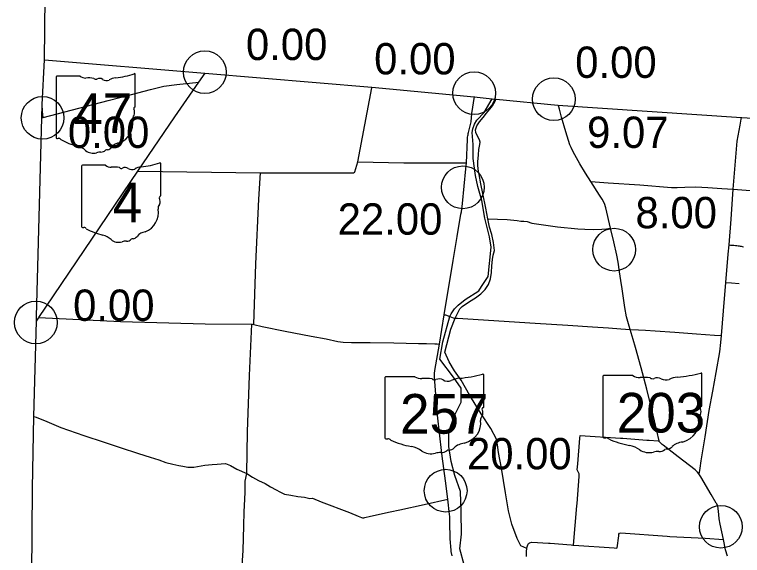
# Model space of a CAD drawing. Extents: x 1597222 to 1925846, y 496284 to 911751.
# Drawn here: x 1759112 to 1784691, y 873644 to 892633 of the extents above; entities that cross this region are included whole.
import ezdxf

# ---------------------------------------------------------------- set-up
doc = ezdxf.new("R2010")
doc.units = 0
for name, color, linetype in [('Default', 7, 'Continuous'), ('GM_X_Adjacent_County', 7, 'Continuous'), ('GM_X_County', 7, 'Continuous'), ('GM_X_County_Road', 7, 'Continuous'), ('GM_X_State_Route', 7, 'Continuous'), ('GM_X_State_Shield', 7, 'Continuous'), ('GM_X_Township', 7, 'Continuous'), ('GM_X_Township_Road', 7, 'Continuous')]:
    doc.layers.add(name, color=color, linetype=linetype)

msp = doc.modelspace()

# ---------------------------------------------------------------- linework, layer by layer
at = {"layer": 'Default'}
for centre in [(1765798, 890612), (1765798, 890612), (1775265, 889876), (1775265, 889876), (1778064, 889660), (1778064, 889660), (1760098, 889010), (1760098, 889010), (1774865, 886568), (1780183, 884380), (1759862, 881825), (1759862, 881825), (1774262, 875917), (1783934, 874652)]:
    msp.add_circle(centre, 750, dxfattribs=at)
at = {"layer": 'GM_X_Adjacent_County'}
msp.add_line((1760161, 891042), (1760364, 911751), dxfattribs=at)
at = {"layer": 'GM_X_County'}
msp.add_lwpolyline([(1759615, 862978), (1759631, 865937), (1759690, 868390), (1759745, 876009), (1759795, 878524), (1759881, 881868), (1759886, 882027), (1760071, 889009), (1760084, 889480), (1760161, 891042), (1765804, 890577), (1771666, 890080), (1775269, 889747), (1775894, 889674), (1776032, 889658), (1778209, 889456), (1784657, 889014), (1789933, 888711), (1791146, 888682), (1797651, 888237), (1803655, 887971)], dxfattribs=at)
at = {"layer": 'GM_X_County_Road'}
for points in [[(1783164, 876512), (1783184, 876554), (1783209, 876711), (1783243, 876961), (1783384, 877811), (1783523, 878729), (1783651, 879411), (1783765, 880071), (1783893, 880796), (1783932, 881116), (1783954, 881366), (1784027, 882233), (1784112, 883231), (1784194, 884219), (1784219, 884544), (1784290, 885451), (1784371, 886499), (1784505, 888183), (1784615, 888751), (1784662, 889026)], [(1779364, 886770), (1779967, 886729), (1781087, 886653), (1782198, 886565), (1782396, 886560), (1782670, 886574), (1783048, 886584), (1783473, 886564), (1783964, 886527), (1784371, 886499), (1786660, 886325), (1787926, 886227), (1788905, 886151), (1789695, 886094), (1789778, 886088), (1790812, 886013), (1791205, 885983), (1792690, 885877), (1793992, 885783), (1794775, 885730), (1796902, 885573), (1797304, 885549), (1797451, 885547), (1797502, 885545)], [(1759969, 881997), (1762841, 881858), (1765814, 881778), (1767451, 881759), (1767471, 881758), (1767516, 881753), (1767813, 881684), (1768617, 881522), (1769536, 881337), (1770062, 881247), (1770477, 881159), (1770666, 881130), (1770953, 881125), (1771606, 881121), (1772443, 881104), (1773313, 881088), (1773587, 881081), (1773877, 881076), (1773962, 881074), (1774048, 881064)], [(1774211, 882090), (1774252, 882089), (1774404, 882033)], [(1774404, 882033), (1774406, 882032), (1774523, 881989), (1774565, 881978), (1774598, 881976), (1774681, 881977), (1777408, 881796), (1778560, 881723), (1779427, 881668), (1779984, 881633), (1780423, 881605), (1780749, 881582)], [(1759795, 878524), (1759874, 878494), (1760252, 878350), (1760733, 878141), (1761552, 877854), (1762256, 877623), (1762819, 877435), (1763473, 877228), (1763875, 877098), (1764180, 876995), (1764428, 876912), (1764673, 876852), (1764882, 876805), (1765024, 876776), (1765203, 876738), (1765411, 876747), (1765804, 876809), (1766052, 876831), (1766236, 876847), (1766368, 876855), (1766526, 876867), (1766703, 876800), (1766927, 876678), (1767271, 876519)], [(1767271, 876519), (1767477, 876397), (1767681, 876278), (1767921, 876172), (1768111, 876051), (1768305, 875950), (1768436, 875882), (1768593, 875793), (1768820, 875758), (1769062, 875716), (1769301, 875685), (1769490, 875642), (1769580, 875657), (1769884, 875528), (1770879, 875150), (1771192, 875019), (1771304, 874972), (1771344, 874966), (1771384, 874967), (1771424, 874974), (1771622, 875018), (1772316, 875174), (1772655, 875249), (1773509, 875437), (1774333, 875620)]]:
    msp.add_lwpolyline(points, dxfattribs=at)
at = {"layer": 'GM_X_State_Route'}
for points in [[(1759881, 881868), (1759956, 881980), (1759969, 881997), (1763443, 887141), (1764744, 889038), (1765591, 890255), (1765808, 890573)], [(1760071, 889009), (1760118, 889022), (1762397, 889618), (1763225, 889831), (1763889, 890004), (1764355, 890118), (1764820, 890175), (1765591, 890255)], [(1774491, 873632), (1774460, 873783), (1774453, 873834), (1774417, 874231), (1774413, 874823), (1774404, 875011), (1774397, 875080), (1774333, 875620), (1774258, 876258), (1774139, 877129), (1774064, 877743), (1773968, 878674), (1773866, 879905), (1773869, 880029), (1773882, 880140), (1774048, 881064), (1774211, 882090), (1774530, 884003), (1774667, 884846), (1774801, 885624), (1774814, 885707), (1774851, 886003), (1774976, 887219), (1774992, 887423), (1775028, 888248), (1775030, 888289), (1775035, 888331), (1775040, 888372), (1775048, 888413), (1775057, 888454), (1775067, 888494), (1775128, 888732), (1775139, 888776), (1775154, 888865), (1775187, 889163), (1775276, 889757)], [(1784162, 873624), (1784100, 873843), (1784021, 874208), (1783910, 874738), (1783876, 874927), (1783859, 875086), (1783838, 875289), (1783833, 875317), (1783827, 875344), (1783809, 875398), (1783786, 875450), (1783772, 875475), (1783588, 875783), (1783232, 876403), (1783164, 876512), (1783115, 876570), (1783035, 876646), (1782427, 877101), (1781907, 877510), (1781873, 877541), (1781822, 877589), (1781780, 877630), (1781764, 877670), (1781516, 878719), (1781330, 879483), (1781130, 880233), (1780935, 880943), (1780851, 881229), (1780749, 881582), (1780714, 881694), (1780668, 881862), (1780620, 882022), (1780562, 882353), (1780462, 883009), (1780418, 883294), (1780375, 883601), (1780321, 883942), (1780275, 884187), (1780166, 884660), (1780054, 885130), (1779891, 885844), (1779879, 885886), (1779851, 885966), (1779818, 886043), (1779756, 886154), (1779666, 886298), (1779364, 886770), (1779176, 887069), (1778977, 887392), (1778738, 887817), (1778667, 887962), (1778627, 888061), (1778487, 888517), (1778336, 889030), (1778262, 889312), (1778237, 889390), (1778211, 889454)]]:
    msp.add_lwpolyline(points, dxfattribs=at)
at = {"layer": 'GM_X_State_Shield'}
for p, q in [((1760571, 890435), (1760571, 888322)), ((1760571, 890435), (1760571, 888322)), ((1761414, 890471), (1760599, 890471)), ((1761414, 890471), (1760599, 890471)), ((1763356, 889418), (1763356, 890524)), ((1763356, 889418), (1763356, 890524)), ((1763355, 889418), (1763356, 889418)), ((1763355, 889418), (1763356, 889418)), ((1762312, 887343), (1761496, 887343)), ((1762312, 887343), (1761496, 887343)), ((1764253, 886290), (1764253, 887395)), ((1764253, 886290), (1764253, 887395)), ((1761469, 887306), (1761469, 885193)), ((1761469, 887306), (1761469, 885193)), ((1764253, 886290), (1764253, 886290)), ((1764253, 886290), (1764253, 886290)), ((1773178, 879920), (1772159, 879920)), ((1773178, 879920), (1772159, 879920)), ((1775605, 878867), (1775605, 879972)), ((1775605, 878867), (1775605, 879972)), ((1779789, 879923), (1779789, 877810)), ((1779789, 879923), (1779789, 877810)), ((1780843, 879960), (1779823, 879960)), ((1780843, 879960), (1779823, 879960)), ((1783269, 878907), (1783269, 880012)), ((1783269, 878907), (1783269, 880012)), ((1772124, 879884), (1772124, 877770)), ((1772124, 879884), (1772124, 877770)), ((1783269, 878907), (1783269, 878907)), ((1783269, 878907), (1783269, 878907)), ((1775604, 878867), (1775605, 878867)), ((1775604, 878867), (1775605, 878867))]:
    msp.add_line(p, q, dxfattribs=at)
for centre, radius, start, end in [((1760603, 890439), 32.3, 98.1301, 188.1301), ((1760603, 890439), 32.3, 98.1301, 188.1301), ((1761608, 890717), 313, 231.6195, 271.1119), ((1761608, 890717), 313, 231.6195, 271.1119), ((1761712, 889285), 1123, 80.4867, 94.9883), ((1761712, 889285), 1123, 80.4867, 94.9883), ((1762741, 889826), 594, 97.3462, 120.7689), ((1762741, 889826), 594, 97.3462, 120.7689), ((1762364, 893352), 2953, 275.8445, 288.9065), ((1762364, 893352), 2953, 275.8445, 288.9065), ((1763325, 890528), 31, 351.8621, 97.738), ((1763325, 890528), 31, 351.8621, 97.738), ((1761967, 890450), 90.3, 219.7921, 297.1024), ((1761967, 890450), 90.3, 219.7921, 297.1024), ((1762100, 890206), 188, 54.4667, 119.1411), ((1762100, 890206), 188, 54.4667, 119.1411), ((1762342, 890541), 226, 233.8562, 294.8282), ((1762342, 890541), 226, 233.8562, 294.8282), ((1763349, 889337), 48, 107.944, 210.337), ((1763349, 889337), 48, 107.944, 210.337), ((1763323, 889414), 33.2, 289.6038, 7.7341), ((1763323, 889414), 33.2, 289.6038, 7.7341), ((1763043, 889197), 288, 340.033, 23.6496), ((1763043, 889197), 288, 340.033, 23.6496), ((1762529, 888815), 739, 292.3089, 8.9858), ((1762529, 888815), 739, 292.3089, 8.9858), ((1763467, 888955), 210, 136.8065, 186.9296), ((1763467, 888955), 210, 136.8065, 186.9296), ((1760604, 888317), 32.5, 171.9584, 258.3066), ((1760604, 888317), 32.5, 171.9584, 258.3066), ((1760609, 888533), 248, 267.339, 280.6039), ((1760609, 888533), 248, 267.339, 280.6039), ((1760659, 888200), 89.5, 29.7484, 93.2717), ((1760659, 888200), 89.5, 29.7484, 93.2717), ((1761790, 890098), 2132, 240.4129, 257.1985), ((1761790, 890098), 2132, 240.4129, 257.1985), ((1762841, 887728), 404, 94.4031, 142.5768), ((1762841, 887728), 404, 94.4031, 142.5768), ((1761154, 887372), 667, 47.1842, 75.836), ((1761154, 887372), 667, 47.1842, 75.836), ((1761876, 888189), 423, 230.7004, 286.2918), ((1761876, 888189), 423, 230.7004, 286.2918), ((1762151, 888031), 226, 268.777, 315.5493), ((1762151, 888031), 226, 268.777, 315.5493), ((1762355, 887826), 63.5, 65.7517, 132.6484), ((1762355, 887826), 63.5, 65.7517, 132.6484), ((1762328, 888117), 239, 282.8732, 323.2771), ((1762328, 888117), 239, 282.8732, 323.2771), ((1762120, 887459), 348, 85.6951, 111.2099), ((1762120, 887459), 348, 85.6951, 111.2099), ((1761501, 887311), 32.3, 98.1301, 188.1301), ((1761501, 887311), 32.3, 98.1301, 188.1301), ((1762506, 887588), 313, 231.6195, 271.1119), ((1762506, 887588), 313, 231.6195, 271.1119), ((1763261, 890224), 2953, 275.8445, 288.9065), ((1763261, 890224), 2953, 275.8445, 288.9065), ((1764222, 887400), 31, 351.8621, 97.738), ((1764222, 887400), 31, 351.8621, 97.738), ((1762610, 886156), 1123, 80.4867, 94.9883), ((1762610, 886156), 1123, 80.4867, 94.9883), ((1762865, 887322), 90.3, 219.7921, 297.1024), ((1762865, 887322), 90.3, 219.7921, 297.1024), ((1762997, 887078), 188, 54.4667, 119.1411), ((1762997, 887078), 188, 54.4667, 119.1411), ((1763239, 887413), 226, 233.8562, 294.8282), ((1763239, 887413), 226, 233.8562, 294.8282), ((1763638, 886697), 594, 97.3462, 120.7689), ((1763638, 886697), 594, 97.3462, 120.7689), ((1764246, 886209), 48, 107.944, 210.337), ((1764246, 886209), 48, 107.944, 210.337), ((1763941, 886069), 288, 340.033, 23.6496), ((1763941, 886069), 288, 340.033, 23.6496), ((1764220, 886285), 33.2, 289.6038, 7.7341), ((1764220, 886285), 33.2, 289.6038, 7.7341), ((1763427, 885686), 739, 292.3089, 8.9858), ((1763427, 885686), 739, 292.3089, 8.9858), ((1764364, 885827), 210, 136.8065, 186.9296), ((1764364, 885827), 210, 136.8065, 186.9296), ((1761501, 885189), 32.5, 171.9584, 258.3066), ((1761501, 885189), 32.5, 171.9584, 258.3066), ((1761506, 885405), 248, 267.339, 280.6039), ((1761506, 885405), 248, 267.339, 280.6039), ((1761557, 885071), 89.5, 29.7484, 93.2717), ((1761557, 885071), 89.5, 29.7484, 93.2717), ((1762687, 886970), 2132, 240.4129, 257.1985), ((1762687, 886970), 2132, 240.4129, 257.1985), ((1762052, 884244), 667, 47.1842, 75.836), ((1762052, 884244), 667, 47.1842, 75.836), ((1763226, 884988), 239, 282.8732, 323.2771), ((1763226, 884988), 239, 282.8732, 323.2771), ((1763738, 884600), 404, 94.4031, 142.5768), ((1763738, 884600), 404, 94.4031, 142.5768), ((1762773, 885061), 423, 230.7004, 286.2918), ((1762773, 885061), 423, 230.7004, 286.2918), ((1763018, 884330), 348, 85.6951, 111.2099), ((1763018, 884330), 348, 85.6951, 111.2099), ((1763049, 884903), 226, 268.777, 315.5493), ((1763049, 884903), 226, 268.777, 315.5493), ((1763253, 884698), 63.5, 65.7517, 132.6484), ((1763253, 884698), 63.5, 65.7517, 132.6484)]:
    msp.add_arc(centre, radius, start, end, dxfattribs=at)
for centre, major_axis, start_param, end_param in [((1772164, 879888), (40.3, 0), 1.712693, 3.28349), ((1772164, 879888), (40.3, 0), 1.712693, 3.28349), ((1773421, 880165), (391, 0), 4.042523, 4.731795), ((1773421, 880165), (391, 0), 4.042523, 4.731795), ((1774365, 882801), (3691, 0), 4.814394, 5.042369), ((1774365, 882801), (3691, 0), 4.814394, 5.042369), ((1775566, 879977), (38.7, 0), 6.141152, 7.989035), ((1775566, 879977), (38.7, 0), 6.141152, 7.989035), ((1779829, 879928), (40.3, 0), 1.712693, 3.28349), ((1779829, 879928), (40.3, 0), 1.712693, 3.28349), ((1781085, 880205), (391, 0), 4.042523, 4.731795), ((1781085, 880205), (391, 0), 4.042523, 4.731795), ((1782030, 882841), (3691, 0), 4.814394, 5.042369), ((1782030, 882841), (3691, 0), 4.814394, 5.042369), ((1783231, 880017), (38.7, 0), 6.141152, 7.989035), ((1783231, 880017), (38.7, 0), 6.141152, 7.989035), ((1773550, 878734), (1404, 0), 1.404758, 1.657858), ((1773550, 878734), (1404, 0), 1.404758, 1.657858), ((1773869, 879899), (113, 0), 3.836095, 5.185415), ((1773869, 879899), (113, 0), 3.836095, 5.185415), ((1774035, 879655), (235, 0), 0.950623, 2.079405), ((1774035, 879655), (235, 0), 0.950623, 2.079405), ((1774337, 879990), (282, 0), 4.081561, 5.145723), ((1774337, 879990), (282, 0), 4.081561, 5.145723), ((1774836, 879275), (743, 0), 1.699011, 2.107814), ((1774836, 879275), (743, 0), 1.699011, 2.107814), ((1781215, 878773), (1404, 0), 1.404758, 1.657858), ((1781215, 878773), (1404, 0), 1.404758, 1.657858), ((1781534, 879939), (113, 0), 3.836095, 5.185415), ((1781534, 879939), (113, 0), 3.836095, 5.185415), ((1781699, 879694), (235, 0), 0.950623, 2.079405), ((1781699, 879694), (235, 0), 0.950623, 2.079405), ((1782002, 880030), (282, 0), 4.081561, 5.145723), ((1782002, 880030), (282, 0), 4.081561, 5.145723), ((1782500, 879314), (743, 0), 1.699011, 2.107814), ((1782500, 879314), (743, 0), 1.699011, 2.107814), ((1783228, 878902), (41.5, 0), 5.05454, 6.418171), ((1783228, 878902), (41.5, 0), 5.05454, 6.418171), ((1775596, 878786), (60, 0), 1.883978, 3.671073), ((1775596, 878786), (60, 0), 1.883978, 3.671073), ((1775214, 878646), (360, 0), 5.934695, 6.695948), ((1775214, 878646), (360, 0), 5.934695, 6.695948), ((1775563, 878863), (41.5, 0), 5.05454, 6.418171), ((1775563, 878863), (41.5, 0), 5.05454, 6.418171), ((1783260, 878825), (60, 0), 1.883978, 3.671073), ((1783260, 878825), (60, 0), 1.883978, 3.671073), ((1782879, 878686), (360, 0), 5.934695, 6.695948), ((1782879, 878686), (360, 0), 5.934695, 6.695948), ((1774572, 878264), (923, 0), 5.101752, 6.440018), ((1774572, 878264), (923, 0), 5.101752, 6.440018), ((1775743, 878404), (262, 0), 2.387724, 3.262537), ((1775743, 878404), (262, 0), 2.387724, 3.262537), ((1782236, 878303), (923, 0), 5.101752, 6.440018), ((1782236, 878303), (923, 0), 5.101752, 6.440018), ((1783408, 878444), (262, 0), 2.387724, 3.262537), ((1783408, 878444), (262, 0), 2.387724, 3.262537), ((1772164, 877766), (40.7, 0), 3.00124, 4.508301), ((1772164, 877766), (40.7, 0), 3.00124, 4.508301), ((1772171, 877982), (310, 0), 4.665946, 4.897461), ((1772171, 877982), (310, 0), 4.665946, 4.897461), ((1772234, 877649), (112, 0), 0.519207, 1.627899), ((1772234, 877649), (112, 0), 0.519207, 1.627899), ((1773647, 879547), (2665, 0), 4.195997, 4.488961), ((1773647, 879547), (2665, 0), 4.195997, 4.488961), ((1779829, 877805), (40.7, 0), 3.00124, 4.508301), ((1779829, 877805), (40.7, 0), 3.00124, 4.508301), ((1779835, 878022), (310, 0), 4.665946, 4.897461), ((1779835, 878022), (310, 0), 4.665946, 4.897461), ((1779899, 877688), (112, 0), 0.519207, 1.627899), ((1779899, 877688), (112, 0), 0.519207, 1.627899), ((1781312, 879587), (2665, 0), 4.195997, 4.488961), ((1781312, 879587), (2665, 0), 4.195997, 4.488961), ((1782626, 877217), (506, 0), 1.647645, 2.488434), ((1782626, 877217), (506, 0), 1.647645, 2.488434), ((1772853, 876821), (834, 0), 0.823519, 1.323587), ((1772853, 876821), (834, 0), 0.823519, 1.323587), ((1774320, 877566), (298, 0), 4.937069, 5.64225), ((1774320, 877566), (298, 0), 4.937069, 5.64225), ((1774961, 877177), (506, 0), 1.647645, 2.488434), ((1774961, 877177), (506, 0), 1.647645, 2.488434), ((1780518, 876861), (834, 0), 0.823519, 1.323587), ((1780518, 876861), (834, 0), 0.823519, 1.323587), ((1781764, 877519), (282, 0), 4.691044, 5.507374), ((1781764, 877519), (282, 0), 4.691044, 5.507374), ((1782019, 877315), (79.4, 0), 1.147584, 2.315152), ((1782019, 877315), (79.4, 0), 1.147584, 2.315152), ((1781985, 877605), (298, 0), 4.937069, 5.64225), ((1781985, 877605), (298, 0), 4.937069, 5.64225), ((1773755, 877638), (529, 0), 4.026481, 4.996735), ((1773755, 877638), (529, 0), 4.026481, 4.996735), ((1774060, 876907), (435, 0), 1.495662, 1.94098), ((1774060, 876907), (435, 0), 1.495662, 1.94098), ((1774099, 877480), (282, 0), 4.691044, 5.507374), ((1774099, 877480), (282, 0), 4.691044, 5.507374), ((1774354, 877275), (79.4, 0), 1.147584, 2.315152), ((1774354, 877275), (79.4, 0), 1.147584, 2.315152), ((1781419, 877678), (529, 0), 4.026481, 4.996735), ((1781419, 877678), (529, 0), 4.026481, 4.996735), ((1781725, 876947), (435, 0), 1.495662, 1.94098), ((1781725, 876947), (435, 0), 1.495662, 1.94098)]:
    msp.add_ellipse(centre, major_axis=major_axis, ratio=0.8, start_param=start_param, end_param=end_param, dxfattribs=at)
at = {"layer": 'GM_X_Township'}
msp.add_lwpolyline([(1774908, 873319), (1774761, 873873), (1774819, 874386), (1774803, 875172), (1774782, 875893), (1774586, 876451), (1774457, 876944), (1774369, 877473), (1774370, 877987), (1774561, 878529), (1774803, 879020), (1774811, 879521), (1774533, 879901), (1774059, 880530), (1774167, 881144), (1774406, 882032), (1774456, 882123), (1774578, 882303), (1774707, 882427), (1774948, 882624), (1775424, 882934), (1775526, 883091), (1775753, 883439), (1775862, 884465), (1775797, 884834), (1775636, 885483), (1775537, 886105), (1775391, 886594), (1775307, 886986), (1775234, 887582), (1775230, 888073), (1775193, 888494), (1775219, 888624), (1775271, 888791), (1775360, 888928), (1775618, 889192), (1775894, 889674)], dxfattribs=at)
at = {"layer": 'GM_X_Township_Road'}
for points in [[(1763443, 887141), (1767751, 887076), (1767754, 887076), (1771026, 887079), (1771060, 887099), (1771076, 887115), (1771171, 887463), (1771666, 890061)], [(1774598, 881976), (1774720, 882234), (1774760, 882299), (1774813, 882356), (1774843, 882381), (1775103, 882554), (1775313, 882683), (1775499, 882831), (1775649, 882983), (1775766, 883156), (1775837, 883357), (1775874, 883577), (1775887, 883810), (1775907, 884030), (1775933, 884182), (1775979, 884346), (1775947, 884626), (1775885, 884907), (1775798, 885171), (1775741, 885463), (1775674, 885840), (1775571, 886351), (1775497, 886692), (1775435, 887014), (1775403, 887209), (1775389, 887360), (1775389, 887468), (1775413, 887707), (1775432, 887898), (1775464, 888072), (1775469, 888156), (1775448, 888237), (1775365, 888393), (1775328, 888495), (1775314, 888590), (1775354, 888724), (1775454, 888867), (1775584, 889017), (1775702, 889168), (1775820, 889307), (1775910, 889426), (1775960, 889506), (1776017, 889615), (1776026, 889659)], [(1760118, 889022), (1760097, 889226), (1760084, 889480)], [(1771171, 887463), (1772796, 887430), (1772896, 887428), (1774620, 887429), (1774992, 887423)], [(1767516, 881753), (1767592, 883879), (1767693, 886154), (1767751, 887076)], [(1775741, 885463), (1776426, 885437), (1776777, 885403), (1776902, 885381), (1777004, 885378), (1777125, 885372), (1777289, 885315), (1778196, 885185), (1778905, 885114), (1779153, 885103), (1779444, 885093), (1779746, 885100), (1779909, 885109), (1779987, 885117), (1780054, 885130)], [(1784219, 884544), (1784275, 884542), (1784330, 884538), (1784387, 884534), (1784447, 884529), (1784491, 884526), (1784544, 884519), (1784576, 884515), (1784610, 884507), (1784645, 884498), (1784687, 884486), (1784724, 884474)], [(1784112, 883231), (1784306, 883215), (1784581, 883194)], [(1777098, 873608), (1777104, 873680), (1777108, 873786), (1777112, 873891), (1776901, 873984), (1776777, 874239), (1776590, 874743), (1776465, 875214), (1776369, 875841), (1776222, 876705), (1776122, 877260), (1776082, 877522), (1776051, 877721), (1775845, 878101), (1775513, 878619), (1775109, 879262), (1774809, 879796), (1774568, 880125), (1774383, 880446), (1774238, 880775), (1774441, 881584), (1774598, 881976)], [(1767271, 876519), (1767296, 877988), (1767372, 879961), (1767451, 881759)], [(1780749, 881582), (1781033, 881565), (1781283, 881552), (1781619, 881527), (1782312, 881487), (1783082, 881429), (1783715, 881383), (1783954, 881366)], [(1778760, 874006), (1778875, 875382), (1778882, 875465), (1778952, 876413), (1778959, 876509), (1778911, 876603), (1778883, 876655), (1778897, 876760), (1778909, 876862), (1778976, 877757), (1778983, 877852), (1780406, 877766), (1780489, 877760), (1781332, 877695), (1781408, 877688), (1781724, 877665), (1781764, 877670)], [(1768190, 870136), (1768081, 870244), (1767947, 870409), (1767861, 870528), (1767742, 870726), (1767651, 870916), (1767543, 871171), (1767459, 871342), (1767376, 871496), (1767334, 871653), (1767253, 872089), (1767171, 872502), (1767108, 872731), (1767120, 873106), (1767121, 873461), (1767150, 873817), (1767171, 874681), (1767185, 875170), (1767198, 875395), (1767211, 875858), (1767213, 876255), (1767271, 876519)], [(1778734, 874009), (1778760, 874006), (1778766, 874006), (1780188, 873906), (1780264, 873900), (1780288, 873916), (1780344, 874335), (1780352, 874393), (1780370, 874430), (1780414, 874432), (1782047, 874317), (1782140, 874310), (1783379, 874247), (1784021, 874208)], [(1777112, 873891), (1777129, 873941), (1777152, 874011), (1777174, 874061), (1777204, 874087), (1777296, 874115), (1777876, 874078), (1777937, 874074), (1778674, 874014), (1778730, 874009), (1778734, 874009)]]:
    msp.add_lwpolyline(points, dxfattribs=at)

# ---------------------------------------------------------------- texts
at = {"layer": 'Default'}
for s, p in [('0.00', (1767243, 891037)), ('0.00', (1771748, 890533)), ('0.00', (1778814, 890410)), ('0.00', (1760987, 887951)), ('9.07', (1779232, 887951)), ('8.00', (1780933, 885130)), ('22.00', (1770467, 884906)), ('0.00', (1761169, 881879)), ('20.00', (1775012, 876667))]:
    msp.add_text(s, height=1100, dxfattribs=at).set_placement(p)
at = {"layer": 'GM_X_State_Shield'}
for s, height, p in [('47', 1392.2, (1761177, 888471)), ('47', 1392.2, (1761177, 888471)), ('4', 1392, (1762565, 885342)), ('4', 1392, (1762565, 885342)), ('257', 1392.2, (1772660, 877919)), ('257', 1392.2, (1772660, 877919)), ('203', 1392.2, (1780274, 877959)), ('203', 1392.2, (1780274, 877959))]:
    msp.add_text(s, height=height, dxfattribs=at).set_placement(p)

doc.saveas('drawing.dxf')
